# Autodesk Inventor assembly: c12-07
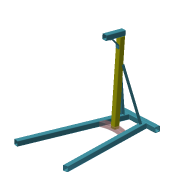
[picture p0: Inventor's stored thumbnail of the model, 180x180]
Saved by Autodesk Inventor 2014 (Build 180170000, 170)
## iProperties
Created: 2011-01
Part Number: c12-07
Document SubType Name: Assembly
Designer: Thom Tremblay
_SolveAssemblyDoc: Frame Generator Solve Assembly
_Version: 15.0.0
Author: Thom Tremblay
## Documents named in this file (3)
- C:\Inventor 2014 Essentials\Assemblies\Chapter 12\c12-07.iam
- C:\Inventor 2014 Essentials\Assemblies\Chapter 12\Frame\Frame c12-07.iam
- C:\Inventor 2014 Essentials\Parts\Chapter 12\c12-02.ipt
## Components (2 placed, 2 different names)
1. c12-02:1
2. Frame c12-07:1 [sub-assembly]
